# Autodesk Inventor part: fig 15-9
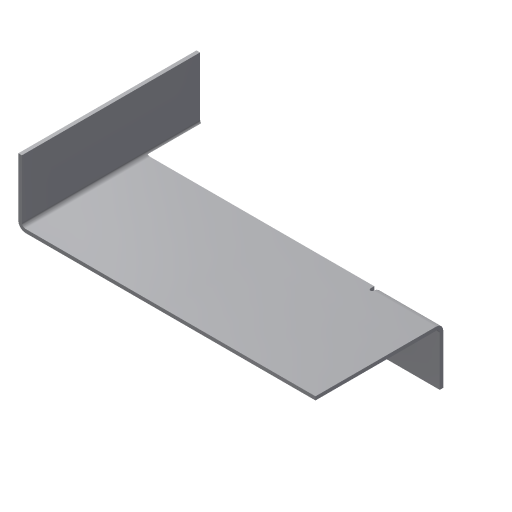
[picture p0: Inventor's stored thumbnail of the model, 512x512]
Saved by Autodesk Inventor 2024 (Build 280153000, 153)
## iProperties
Shininess: 77.0
Angle Display Precision: 2
Document Length Units: 11269
Document Angle Units: 11279
Document Time Units: 11290
Document Mass Units: 11283
Document Length Units Precision: 3
Document Angle Units Precision: 2
Created: 2002-04
Part Number: fig 15-9
Material: Aluminum-6061
Document SubType Name: Sheet Metal
Density: 1 g/cm^3
Sheet Metal Rule: Default
Appearance: Aluminum - Flat-1
Density: 0.0
Volumn: 0.0
Area: 0.0
PropertySet Name: Model Information
Control State: 0
Master: False
Checked Out: False
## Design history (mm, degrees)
node "Face1"
  sketch "Sketch1"
    geometry: L1 (-49.559, 19.574)-(-49.559, -30.426); L2 (-49.559, -30.426)-(50.441, -30.426); L3 (50.441, -30.426)-(50.441, 19.574); L4 (50.441, 19.574)-(32.941, 19.574); L5 (32.941, 19.574)-(32.941, 4.574); L6 (32.941, 4.574)-(-32.059, 4.574); L7 (-32.059, 4.574)-(-32.059, 19.574); L8 (-32.059, 19.574)-(-49.559, 19.574)
    constraints: 16 end point, 6 parallel, 2 equal length, 1 perpendicular, 1 vertical
    dimensions: "d0" = 100 distance of L1.end L2.end; "d1" = 65 distance of L5.end L6.end; "d2" = 15 distance of L6.end L7.end; "d3" = 50 distance of L1.start L1.end
feature "Fold2" dims "d8" = 1 (= BendRadius), "d9" = 90 deg, "d10" = 1 (= BendRadius), "d14" = 1 (= BendReliefWidth), "d15" = 0.5 (= BendReliefDepth), "d16" = 2 (= MinimumRemnant), "d20" = 1 (= Thickness), "SeamGap" = 0.01
feature "Fold3" dims "d11" = 1 (= BendRadius), "d12" = 90 deg, "d13" = 1 (= BendRadius), "d17" = 1 (= BendReliefWidth), "d18" = 0.5 (= BendReliefDepth), "d19" = 2 (= MinimumRemnant), "d20" = 1 (= Thickness), "SeamGap" = 0.01
body "Solid1"
sketch "Sketch2"
  geometry: L1 (100, 0)-(0, 0) reference; L2 (17.5, 50)-(17.5, 35) reference; L3 (82.5, 50)-(82.5, 0)
  constraints: 2 end point, 1 parallel, 1 point on line
face "Plate1" dims "d20" = 1 (= Thickness)
sketch "Sketch3"
  geometry: L1 (81.369, -50)-(0, -50) reference; L2 (17.5, 0)-(17.5, -50)
  constraints: 2 end point, 1 perpendicular, 1 point on line
sketch "Sketch4"
  geometry: L1 (17.5, 0)-(17.5, -50) reference; L2 (-63.869, -15)-(0, -15) reference; L3 (0, -15)-(17.5, -15)
  constraints: 2 end point, 1 collinear, 1 point on line
other parameters: "Thickness" = 1, "BendRadius" = 1 (= Thickness), "BendReliefWidth" = 1 (= Thickness), "BendReliefDepth" = 0.5 (= 0.5 x Thickness), "CornerReliefSize" = 4 (= 4 x Thickness), "MinimumRemnant" = 2 (= 2 x Thickness), "TransitionRadius" = 1 (= BendRadius), "d4" = 1 (= BendRadius), "JacobiRadiusSize" = 1 (= Thickness), "GapSize" = 1 (= Thickness)
